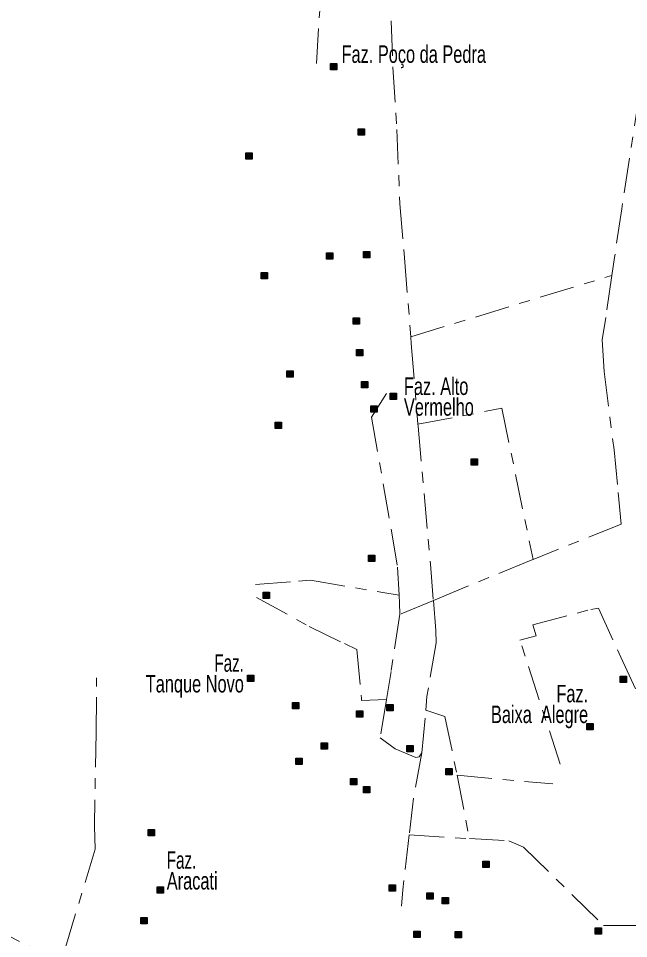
# Model space of a CAD drawing. Extents: x 445.4 to 500, y 8728.7 to 8784.
# Drawn here: x 469.67 to 475.26, y 8770.25 to 8778.68 of the extents above; entities that cross this region are included whole.
import ezdxf
from ezdxf.enums import TextEntityAlignment as Align

# ---------------------------------------------------------------- set-up
doc = ezdxf.new("R2010")
doc.units = 0
doc.header["$LTSCALE"] = 0.064
doc.linetypes.add('DOT_DASHED', pattern=[7.7, 5, -1.2, 0.3, -1.2])
doc.layers.add('2', color=7, linetype='Continuous', lineweight=25)
doc.layers.add('22', color=7, linetype='DOT_DASHED', lineweight=13)
doc.layers.add('61', color=7, linetype='Continuous')

msp = doc.modelspace()

# ---------------------------------------------------------------- hatches: boundary and pattern name
at = {"layer": '2'}
for points in [[(472.5261, 8778.2636), (472.5841, 8778.2636), (472.5841, 8778.2056), (472.5261, 8778.2056)], [(472.7792, 8777.664), (472.8372, 8777.664), (472.8372, 8777.606), (472.7792, 8777.606)], [(471.7523, 8777.4441), (471.8103, 8777.4441), (471.8103, 8777.3861), (471.7523, 8777.3861)], [(472.4899, 8776.5297), (472.5479, 8776.5297), (472.5479, 8776.4717), (472.4899, 8776.4717)], [(472.8287, 8776.5397), (472.8867, 8776.5397), (472.8867, 8776.4817), (472.8287, 8776.4817)], [(471.8926, 8776.3485), (471.9506, 8776.3485), (471.9506, 8776.2905), (471.8926, 8776.2905)], [(472.7343, 8775.9321), (472.7923, 8775.9321), (472.7923, 8775.8741), (472.7343, 8775.8741)], [(472.7659, 8775.6423), (472.8239, 8775.6423), (472.8239, 8775.5843), (472.7659, 8775.5843)], [(472.1279, 8775.4475), (472.1859, 8775.4475), (472.1859, 8775.3895), (472.1279, 8775.3895)], [(472.8097, 8775.3503), (472.8677, 8775.3503), (472.8677, 8775.2923), (472.8097, 8775.2923)], [(473.0736, 8775.2439), (473.1316, 8775.2439), (473.1316, 8775.1859), (473.0736, 8775.1859)], [(472.8971, 8775.1255), (472.9551, 8775.1255), (472.9551, 8775.0675), (472.8971, 8775.0675)], [(472.0193, 8774.9766), (472.0773, 8774.9766), (472.0773, 8774.9186), (472.0193, 8774.9186)], [(473.8157, 8774.6418), (473.8737, 8774.6418), (473.8737, 8774.5838), (473.8157, 8774.5838)], [(472.8745, 8773.7589), (472.9325, 8773.7589), (472.9325, 8773.7009), (472.8745, 8773.7009)], [(471.9107, 8773.4192), (471.9687, 8773.4192), (471.9687, 8773.3612), (471.9107, 8773.3612)], [(471.7669, 8772.6583), (471.8249, 8772.6583), (471.8249, 8772.6003), (471.7669, 8772.6003)], [(475.1823, 8772.6497), (475.2403, 8772.6497), (475.2403, 8772.5917), (475.1823, 8772.5917)], [(472.1776, 8772.4096), (472.2356, 8772.4096), (472.2356, 8772.3516), (472.1776, 8772.3516)], [(472.7659, 8772.3328), (472.8239, 8772.3328), (472.8239, 8772.2748), (472.7659, 8772.2748)], [(473.042, 8772.3916), (473.1, 8772.3916), (473.1, 8772.3336), (473.042, 8772.3336)], [(474.8746, 8772.2151), (474.9326, 8772.2151), (474.9326, 8772.1571), (474.8746, 8772.1571)], [(472.4401, 8772.0385), (472.4981, 8772.0385), (472.4981, 8771.9805), (472.4401, 8771.9805)], [(473.2275, 8772.0159), (473.2855, 8772.0159), (473.2855, 8771.9579), (473.2275, 8771.9579)], [(472.2093, 8771.898), (472.2673, 8771.898), (472.2673, 8771.84), (472.2093, 8771.84)], [(473.585, 8771.8031), (473.643, 8771.8031), (473.643, 8771.7451), (473.585, 8771.7451)], [(472.7116, 8771.7125), (472.7696, 8771.7125), (472.7696, 8771.6545), (472.7116, 8771.6545)], [(472.8293, 8771.6401), (472.8873, 8771.6401), (472.8873, 8771.5821), (472.8293, 8771.5821)], [(470.8563, 8771.246), (470.9143, 8771.246), (470.9143, 8771.188), (470.8563, 8771.188)], [(473.9243, 8770.9564), (473.9823, 8770.9564), (473.9823, 8770.8984), (473.9243, 8770.8984)], [(473.0646, 8770.7391), (473.1226, 8770.7391), (473.1226, 8770.6811), (473.0646, 8770.6811)], [(470.9378, 8770.7208), (470.9958, 8770.7208), (470.9958, 8770.6628), (470.9378, 8770.6628)], [(473.4085, 8770.6667), (473.4665, 8770.6667), (473.4665, 8770.6087), (473.4085, 8770.6087)], [(473.5488, 8770.6214), (473.6068, 8770.6214), (473.6068, 8770.5634), (473.5488, 8770.5634)], [(470.7885, 8770.4401), (470.8465, 8770.4401), (470.8465, 8770.3821), (470.7885, 8770.3821)], [(473.2908, 8770.3135), (473.3488, 8770.3135), (473.3488, 8770.2555), (473.2908, 8770.2555)], [(473.6692, 8770.3119), (473.7272, 8770.3119), (473.7272, 8770.2539), (473.6692, 8770.2539)], [(474.9515, 8770.3452), (475.0095, 8770.3452), (475.0095, 8770.2872), (474.9515, 8770.2872)]]:
    msp.add_hatch(color=256, dxfattribs=at).paths.add_polyline_path(points)

# ---------------------------------------------------------------- linework, layer by layer
for points in [[(472.5261, 8778.2636), (472.5841, 8778.2636), (472.5841, 8778.2056), (472.5261, 8778.2056)], [(472.7792, 8777.664), (472.8372, 8777.664), (472.8372, 8777.606), (472.7792, 8777.606)], [(471.7523, 8777.4441), (471.8103, 8777.4441), (471.8103, 8777.3861), (471.7523, 8777.3861)], [(472.4899, 8776.5297), (472.5479, 8776.5297), (472.5479, 8776.4717), (472.4899, 8776.4717)], [(472.8287, 8776.5397), (472.8867, 8776.5397), (472.8867, 8776.4817), (472.8287, 8776.4817)], [(471.8926, 8776.3485), (471.9506, 8776.3485), (471.9506, 8776.2905), (471.8926, 8776.2905)], [(472.7343, 8775.9321), (472.7923, 8775.9321), (472.7923, 8775.8741), (472.7343, 8775.8741)], [(472.7659, 8775.6423), (472.8239, 8775.6423), (472.8239, 8775.5843), (472.7659, 8775.5843)], [(472.1279, 8775.4475), (472.1859, 8775.4475), (472.1859, 8775.3895), (472.1279, 8775.3895)], [(472.8097, 8775.3503), (472.8677, 8775.3503), (472.8677, 8775.2923), (472.8097, 8775.2923)], [(473.0736, 8775.2439), (473.1316, 8775.2439), (473.1316, 8775.1859), (473.0736, 8775.1859)], [(472.8971, 8775.1255), (472.9551, 8775.1255), (472.9551, 8775.0675), (472.8971, 8775.0675)], [(472.0193, 8774.9766), (472.0773, 8774.9766), (472.0773, 8774.9186), (472.0193, 8774.9186)], [(473.8157, 8774.6418), (473.8737, 8774.6418), (473.8737, 8774.5838), (473.8157, 8774.5838)], [(472.8745, 8773.7589), (472.9325, 8773.7589), (472.9325, 8773.7009), (472.8745, 8773.7009)], [(471.9107, 8773.4192), (471.9687, 8773.4192), (471.9687, 8773.3612), (471.9107, 8773.3612)], [(471.7669, 8772.6583), (471.8249, 8772.6583), (471.8249, 8772.6003), (471.7669, 8772.6003)], [(475.1823, 8772.6497), (475.2403, 8772.6497), (475.2403, 8772.5917), (475.1823, 8772.5917)], [(472.1776, 8772.4096), (472.2356, 8772.4096), (472.2356, 8772.3516), (472.1776, 8772.3516)], [(472.7659, 8772.3328), (472.8239, 8772.3328), (472.8239, 8772.2748), (472.7659, 8772.2748)], [(473.042, 8772.3916), (473.1, 8772.3916), (473.1, 8772.3336), (473.042, 8772.3336)], [(474.8746, 8772.2151), (474.9326, 8772.2151), (474.9326, 8772.1571), (474.8746, 8772.1571)], [(472.4401, 8772.0385), (472.4981, 8772.0385), (472.4981, 8771.9805), (472.4401, 8771.9805)], [(473.2275, 8772.0159), (473.2855, 8772.0159), (473.2855, 8771.9579), (473.2275, 8771.9579)], [(472.2093, 8771.898), (472.2673, 8771.898), (472.2673, 8771.84), (472.2093, 8771.84)], [(473.585, 8771.8031), (473.643, 8771.8031), (473.643, 8771.7451), (473.585, 8771.7451)], [(472.7116, 8771.7125), (472.7696, 8771.7125), (472.7696, 8771.6545), (472.7116, 8771.6545)], [(472.8293, 8771.6401), (472.8873, 8771.6401), (472.8873, 8771.5821), (472.8293, 8771.5821)], [(470.8563, 8771.246), (470.9143, 8771.246), (470.9143, 8771.188), (470.8563, 8771.188)], [(473.9243, 8770.9564), (473.9823, 8770.9564), (473.9823, 8770.8984), (473.9243, 8770.8984)], [(473.0646, 8770.7391), (473.1226, 8770.7391), (473.1226, 8770.6811), (473.0646, 8770.6811)], [(470.9378, 8770.7208), (470.9958, 8770.7208), (470.9958, 8770.6628), (470.9378, 8770.6628)], [(473.4085, 8770.6667), (473.4665, 8770.6667), (473.4665, 8770.6087), (473.4085, 8770.6087)], [(473.5488, 8770.6214), (473.6068, 8770.6214), (473.6068, 8770.5634), (473.5488, 8770.5634)], [(470.7885, 8770.4401), (470.8465, 8770.4401), (470.8465, 8770.3821), (470.7885, 8770.3821)], [(473.2908, 8770.3135), (473.3488, 8770.3135), (473.3488, 8770.2555), (473.2908, 8770.2555)], [(473.6692, 8770.3119), (473.7272, 8770.3119), (473.7272, 8770.2539), (473.6692, 8770.2539)], [(474.9515, 8770.3452), (475.0095, 8770.3452), (475.0095, 8770.2872), (474.9515, 8770.2872)]]:
    msp.add_lwpolyline(points, close=True, dxfattribs=at)
at = {"layer": '22'}
for p, q in [((473.2625, 8775.7596), (475.1055, 8776.3224)), ((470.3799, 8772.1367), (470.384, 8772.6363)), ((473.4066, 8772.3339), (473.4071, 8772.3337)), ((473.688, 8771.742), (474.5647, 8771.6632)), ((473.2489, 8771.1958), (473.7997, 8771.1626))]:
    msp.add_line(p, q, dxfattribs=at)
for points in [[(473.4215, 8783.2082), (473.4555, 8783.4182), (473.5112, 8783.7269), (472.8373, 8783.7299), (472.8651, 8783.1403), (472.8894, 8782.6418), (472.9436, 8781.4491), (473.0567, 8779.2734), (473.0994, 8778.2292), (473.1347, 8777.6598), (473.1632, 8776.9766), (473.2059, 8776.4832), (473.2624, 8775.7596)], [(472.398, 8778.2635), (472.4425, 8778.968), (472.4596, 8779.3039), (472.5025, 8779.9532)], [(475.5987, 8779.571), (475.5049, 8778.9128), (475.3863, 8778.1926), (475.3626, 8778.0078), (475.196, 8776.9328), (475.1296, 8776.4874), (475.1055, 8776.3224)], [(475.1055, 8776.3224), (475.0488, 8775.9348), (475.0156, 8775.7311), (475.0346, 8775.4421), (475.1248, 8774.7236), (475.1627, 8774.3328), (475.1911, 8774.0438), (474.3833, 8773.7192)], [(473.2624, 8775.7596), (473.2673, 8775.6973), (473.3277, 8774.9578)], [(473.0386, 8775.2388), (472.903, 8775.0223), (473.0855, 8773.9829), (473.1398, 8773.6479), (473.1557, 8773.3918)], [(473.3277, 8774.9578), (474.0978, 8775.1043), (474.3833, 8773.7192)], [(473.3277, 8774.9578), (473.3291, 8774.9401), (473.4434, 8773.6753), (473.4694, 8773.3441)], [(474.3833, 8773.7192), (474.3656, 8773.7121), (473.7393, 8773.4562), (473.4694, 8773.3441), (473.1636, 8773.2171)], [(471.8401, 8773.4891), (472.235, 8773.5196), (472.3433, 8773.5293), (473.0056, 8773.4165), (473.1557, 8773.3918)], [(471.8485, 8773.3724), (472.3322, 8773.1061), (472.6537, 8772.9485), (472.769, 8772.894), (472.8115, 8772.4456), (472.8115, 8772.4274), (473.039, 8772.437)], [(473.1557, 8773.3918), (473.1602, 8773.3196), (473.1636, 8773.2171)], [(473.4694, 8773.3441), (473.491, 8773.0699), (473.4958, 8772.956), (473.4103, 8772.4626), (473.4002, 8772.3386)], [(474.6312, 8771.8448), (474.2625, 8772.9788), (474.4106, 8773.0211), (474.3824, 8773.1197), (474.9114, 8773.2606), (474.9819, 8773.2747), (475.1865, 8772.8238), (475.4413, 8772.2801)], [(473.1636, 8773.2171), (473.0813, 8772.6939), (473.039, 8772.437)], [(473.039, 8772.437), (472.9813, 8772.0862), (473.1209, 8771.9832), (473.3089, 8771.9044), (473.3393, 8771.9105), (473.3636, 8771.9469), (473.4002, 8772.3386)], [(473.4002, 8772.3386), (473.5754, 8772.2809), (473.688, 8771.742), (473.7997, 8771.1624)], [(470.3799, 8772.1367), (470.3634, 8771.2766), (470.3704, 8771.0653), (470.0742, 8770.0861), (470.0522, 8770.0328), (469.5444, 8770.2864), (469.0929, 8769.4693), (468.8954, 8769.3566), (469.2058, 8768.7438), (469.234, 8768.6944), (469.5161, 8768.6944), (470.1227, 8768.7226), (470.3102, 8768.7261)], [(473.3636, 8771.9469), (473.2885, 8771.5312), (473.249, 8771.1958)], [(473.249, 8771.1958), (473.1897, 8770.6929), (473.1776, 8770.5418)], [(473.7997, 8771.1626), (474.1623, 8771.1407), (474.2963, 8771.0843), (474.7477, 8770.6405), (475.0298, 8770.3658), (475.4711, 8770.3657), (475.6389, 8770.3738)]]:
    msp.add_lwpolyline(points, dxfattribs=at)

# ---------------------------------------------------------------- texts
at = {"layer": '61'}
for s, width, p in [('Faz. Poço da Pedra', 0.7, (472.6279, 8778.2693)), ('Faz. Alto', 0.7, (473.1995, 8775.2266)), ('Vermelho', 0.7, (473.1995, 8775.0366)), ('Faz.', 0.65, (471.0266, 8770.8856)), ('Aracati', 0.7, (471.0266, 8770.6956))]:
    msp.add_text(s, height=0.16, dxfattribs=dict(at, width=width)).set_placement(p)
for s, width, p in [('Faz.', 0.65, (471.7331, 8772.6908)), ('Tanque Novo', 0.7, (471.7331, 8772.5008)), ('              Faz.', 0.7, (474.888, 8772.4105)), ('Baixa  Alegre', 0.7, (474.888, 8772.2205))]:
    msp.add_text(s, height=0.16, dxfattribs=dict(at, width=width)).set_placement(p, align=Align.RIGHT)

doc.saveas('drawing.dxf')
